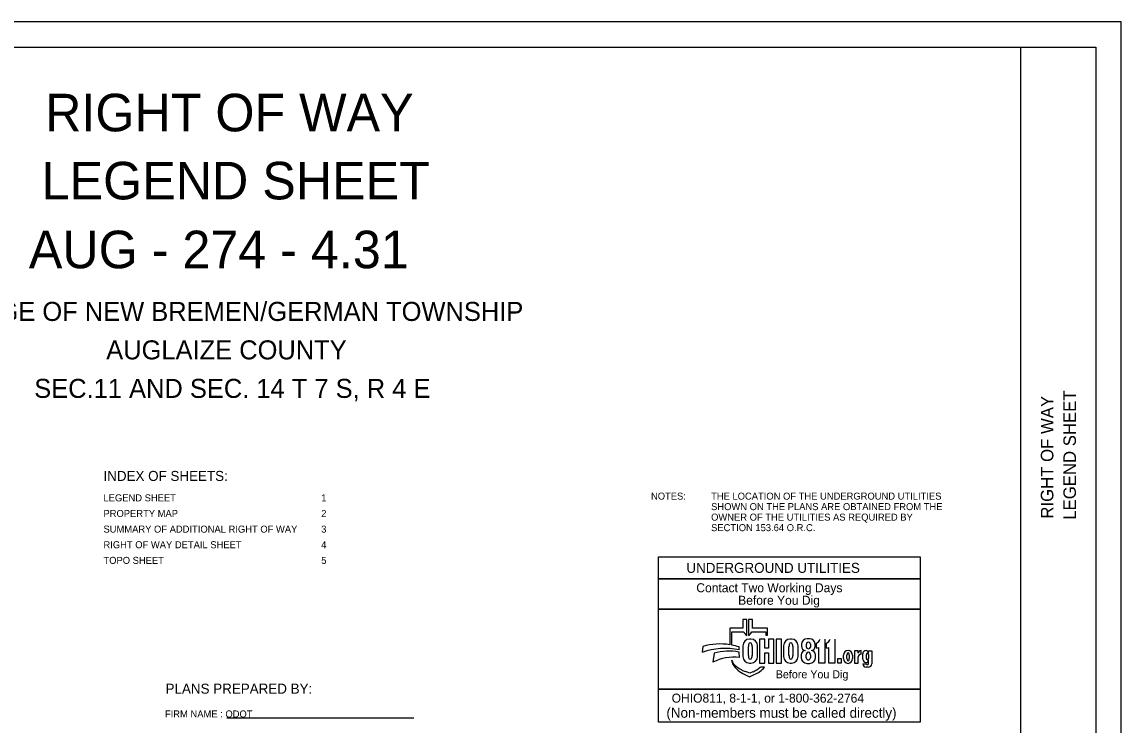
# Model space of a CAD drawing. Extents: x -11.1 to 34, y -3.9 to 22.
# Drawn here: x 12.07 to 34, y 7.96 to 22 of the extents above; entities that cross this region are included whole.
import ezdxf

# ---------------------------------------------------------------- set-up
doc = ezdxf.new("R2010")
doc.units = 0
for name, color, linetype in [('SH_Border', 7, 'Continuous'), ('SH_Cut_Line', 7, 'Continuous'), ('SH_Data', 7, 'Continuous'), ('SH_Text', 7, 'Continuous')]:
    doc.layers.add(name, color=color, linetype=linetype)

msp = doc.modelspace()

# ---------------------------------------------------------------- linework, layer by layer
at = {"layer": 'SH_Border'}
msp.add_line((32, 0.5), (32, 21.5), dxfattribs=at)
msp.add_lwpolyline([(1.5, 21.5), (33.5, 21.5), (33.5, 0.5), (1.5, 0.5)], close=True, dxfattribs=at)
at = {"layer": 'SH_Cut_Line'}
msp.add_lwpolyline([(0, 0), (34, 0), (34, 22), (0, 22)], close=True, dxfattribs=at)
at = {"layer": 'SH_Data'}
for p, q in [((26.455, 9.898), (26.192, 9.898)), ((26.192, 9.898), (26.192, 9.564)), ((26.535, 10.065), (26.455, 10.065)), ((26.455, 10.065), (26.455, 9.898)), ((26.535, 9.748), (26.535, 10.065)), ((26.647, 10.065), (26.566, 10.065)), ((26.566, 10.065), (26.566, 9.748)), ((26.647, 9.898), (26.647, 10.065)), ((26.944, 9.898), (26.647, 9.898)), ((26.944, 9.758), (26.944, 9.898)), ((26.23, 9.557), (26.23, 9.821)), ((26.23, 9.821), (26.471, 9.821)), ((26.612, 9.677), (26.587, 9.677)), ((26.631, 9.821), (26.909, 9.821)), ((26.89, 9.675), (26.788, 9.675)), ((26.788, 9.675), (26.788, 9.197)), ((26.909, 9.821), (26.909, 9.758)), ((26.909, 9.758), (26.944, 9.758)), ((27.423, 9.677), (27.398, 9.677)), ((27.784, 9.683), (27.735, 9.683)), ((28.088, 9.675), (28.088, 9.197)), ((28.288, 9.675), (28.288, 9.197)), ((25.657, 9.529), (25.643, 9.413)), ((26.376, 9.462), (26.376, 9.52)), ((26.454, 9.543), (26.454, 9.331)), ((26.563, 9.348), (26.563, 9.531)), ((26.637, 9.531), (26.637, 9.348)), ((26.746, 9.331), (26.746, 9.543)), ((27.264, 9.543), (27.264, 9.331)), ((27.373, 9.348), (27.373, 9.531)), ((27.448, 9.531), (27.448, 9.348)), ((27.556, 9.331), (27.556, 9.543)), ((27.621, 9.569), (27.621, 9.533)), ((27.72, 9.516), (27.72, 9.575)), ((27.801, 9.575), (27.801, 9.516)), ((27.898, 9.533), (27.898, 9.569)), ((27.921, 9.495), (27.921, 9.597)), ((27.969, 9.197), (27.969, 9.509)), ((28.121, 9.495), (28.121, 9.597)), ((28.169, 9.197), (28.169, 9.509)), ((28.756, 9.441), (28.684, 9.441)), ((28.684, 9.441), (28.684, 9.197)), ((28.756, 9.394), (28.756, 9.441)), ((28.817, 9.449), (28.811, 9.449)), ((28.817, 9.374), (28.817, 9.449)), ((28.96, 9.396), (28.96, 9.442)), ((28.96, 9.442), (29.025, 9.442)), ((29.025, 9.442), (29.025, 9.184)), ((25.878, 9.394), (25.856, 9.215)), ((26.229, 9.258), (26.234, 9.231)), ((26.386, 9.311), (26.377, 9.417)), ((26.89, 9.197), (26.89, 9.4)), ((27.616, 9.363), (27.616, 9.312)), ((27.716, 9.303), (27.716, 9.364)), ((27.801, 9.364), (27.801, 9.303)), ((27.904, 9.312), (27.904, 9.363)), ((28.462, 9.288), (28.462, 9.356)), ((28.529, 9.287), (28.529, 9.356)), ((28.577, 9.356), (28.577, 9.287)), ((28.644, 9.356), (28.644, 9.288)), ((28.756, 9.197), (28.756, 9.325)), ((28.806, 9.374), (28.817, 9.374)), ((28.846, 9.276), (28.846, 9.38)), ((28.918, 9.29), (28.918, 9.366)), ((28.96, 9.366), (28.96, 9.29)), ((28.96, 9.184), (28.96, 9.253)), ((26.594, 8.997), (26.505, 9.027)), ((26.587, 9.197), (26.612, 9.197)), ((26.655, 9.023), (26.594, 8.997)), ((26.788, 9.197), (26.89, 9.197)), ((26.888, 9.117), (26.802, 9.117)), ((26.885, 9.115), (26.888, 9.117)), ((27.398, 9.197), (27.423, 9.197)), ((27.736, 9.191), (27.783, 9.191)), ((28.088, 9.197), (27.969, 9.197)), ((28.288, 9.197), (28.169, 9.197)), ((28.684, 9.197), (28.756, 9.197)), ((28.846, 9.184), (28.918, 9.184)), ((28.956, 9.114), (28.915, 9.114)), ((26.529, 8.951), (26.585, 8.926)), ((26.585, 8.926), (26.68, 8.967)), ((29.991, 8.019), (24.766, 8.019))]:
    msp.add_line(p, q, dxfattribs=at)
for points in [[(24.766, 11.319), (29.991, 11.319), (29.991, 10.879), (24.766, 10.879)], [(24.766, 10.879), (29.991, 10.879), (29.991, 10.274), (24.766, 10.274)], [(24.766, 10.274), (29.991, 10.274), (29.991, 8.679), (24.766, 8.679)], [(28.346, 9.287), (28.412, 9.287), (28.412, 9.197), (28.346, 9.197)], [(24.766, 8.679), (29.991, 8.679), (29.991, 8.019), (24.766, 8.019)]]:
    msp.add_lwpolyline(points, close=True, dxfattribs=at)
for points in [[(26.89, 9.4), (26.966, 9.4), (26.966, 9.197), (27.068, 9.197), (27.068, 9.675), (26.966, 9.675), (26.966, 9.495), (26.89, 9.495), (26.89, 9.675)], [(27.118, 9.197), (27.221, 9.197), (27.221, 9.675), (27.118, 9.675), (27.118, 9.197)], [(27.702, 9.45), (27.702, 9.449)], [(27.817, 9.449), (27.817, 9.45)]]:
    msp.add_lwpolyline(points, dxfattribs=at)
for centre, radius, start, end in [((26.587, 9.543), 0.134, 90, 180), ((26.607, 9.876), 0.147, 201.9296, 240.7469), ((26.495, 9.876), 0.147, 299.2531, 338.0704), ((26.612, 9.543), 0.134, 0, 90), ((27.398, 9.543), 0.134, 90, 180), ((27.423, 9.543), 0.134, 0, 90), ((27.735, 9.569), 0.114, 90, 180), ((27.784, 9.569), 0.114, 0, 90), ((27.87, 9.719), 0.132, 292.5572, 340.7355), ((28.07, 9.719), 0.132, 292.5572, 340.7355), ((26.095, 8.159), 1.332, 77.8238, 109.8274), ((26.001, 8.355), 1.224, 81.0007, 106.3144), ((26.177, 8.342), 1.094, 79.44, 105.8467), ((26.001, 8.355), 1.224, 72.1402, 79.2074), ((27.702, 9.363), 0.0865, 90, 180), ((27.705, 9.533), 0.0837, 180, 268.1442), ((27.814, 9.533), 0.0837, 272.2058, 0), ((27.817, 9.363), 0.0865, 0, 90), ((27.909, 9.627), 0.132, 275.1733, 297.0931), ((28.109, 9.627), 0.132, 275.1733, 297.0931), ((28.557, 9.356), 0.0956, 92.5886, 180), ((28.548, 9.356), 0.0956, 0, 87.4114), ((28.811, 9.394), 0.0548, 90, 180), ((28.914, 9.38), 0.0686, 92.6865, 180), ((28.908, 9.396), 0.0524, 0, 86.9262), ((26.284, 8.367), 0.95, 83.8248, 116.8021), ((26.509, 9.365), 0.3, 201.0457, 232.5314), ((26.445, 9.267), 0.214, 189.6817, 216.0884), ((26.587, 9.331), 0.134, 180, 270), ((26.612, 9.331), 0.134, 270, 0), ((27.398, 9.331), 0.134, 180, 270), ((27.423, 9.331), 0.134, 270, 0), ((27.736, 9.312), 0.121, 180, 270), ((27.783, 9.312), 0.121, 270, 0), ((28.557, 9.288), 0.0956, 180, 267.4114), ((28.548, 9.288), 0.0956, 272.5886, 0), ((28.806, 9.325), 0.0493, 90, 180), ((28.915, 9.276), 0.0692, 180, 265.7132), ((28.914, 9.253), 0.0467, 264.7825, 0), ((26.644, 9.412), 0.461, 216.0884, 235.7167), ((26.797, 9.741), 0.773, 232.5314, 241.794), ((26.893, 9.777), 0.903, 235.7167, 246.2325), ((26.669, 9.503), 0.504, 241.794, 250.9821), ((26.441, 9.517), 0.538, 293.4582, 312.0712), ((26.441, 9.517), 0.599, 293.4582, 317.8286), ((28.915, 9.184), 0.0699, 180, 270), ((28.956, 9.184), 0.0699, 270, 0)]:
    msp.add_arc(centre, radius, start, end, dxfattribs=at)
for centre, major_axis, ratio, start_param, end_param in [((26.6, 9.531), (0, 0.0723), 0.514403, 4.712389, 7.853982), ((27.411, 9.531), (0, 0.0723), 0.514403, 4.712389, 7.853982), ((27.76, 9.575), (0.0404, 0), 0.969373, 0, 3.141593), ((27.76, 9.516), (0.0404, 0), 0.818453, 3.141593, 6.283185), ((26.6, 9.348), (0, 0.0723), 0.514403, 1.570796, 4.712389), ((27.411, 9.348), (0, 0.0723), 0.514403, 1.570796, 4.712389), ((27.759, 9.364), (0, 0.0535), 0.794529, 4.712389, 7.853982), ((27.759, 9.303), (0.0425, 0), 0.959837, 3.141593, 6.283185), ((28.553, 9.356), (0, 0.0434), 0.553236, 4.712389, 7.853982), ((28.553, 9.287), (0, 0.046), 0.522014, 1.570796, 4.712389), ((28.939, 9.366), (0, 0.0275), 0.777179, 4.712389, 7.853982), ((28.939, 9.29), (0, 0.0275), 0.777179, 1.570796, 4.712389), ((28.939, 9.184), (0.0214, 0), 0.959012, 3.141593, 6.283185)]:
    msp.add_ellipse(centre, major_axis=major_axis, ratio=ratio, start_param=start_param, end_param=end_param, dxfattribs=at)
at = {"layer": 'SH_Text'}
msp.add_line((16.151, 8.102), (19.888, 8.102), dxfattribs=at)

# ---------------------------------------------------------------- texts
at = {"layer": 'SH_Data'}
for s, height, p in [('RIGHT OF WAY', 0.75, (12.527, 19.816)), ('LEGEND SHEET', 0.75, (12.458, 18.457)), ('AUG - 274 - 4.31', 0.75, (12.203, 17.082)), ('VILLAGE OF NEW BREMEN/GERMAN TOWNSHIP', 0.38, (10.213, 16.03)), ('AUGLAIZE COUNTY', 0.38, (13.747, 15.262)), ('SEC.11 AND SEC. 14 T 7 S, R 4 E', 0.38, (12.31, 14.493)), ('INDEX OF SHEETS:', 0.2, (13.692, 12.835)), ('LEGEND SHEET', 0.14, (13.692, 12.427)), ('1', 0.14, (18.038, 12.427)), ('PROPERTY MAP', 0.14, (13.692, 12.115)), ('2', 0.14, (18.038, 12.115)), ('SUMMARY OF ADDITIONAL RIGHT OF WAY', 0.14, (13.692, 11.803)), ('3', 0.14, (18.038, 11.803)), ('RIGHT OF WAY DETAIL SHEET', 0.14, (13.692, 11.491)), ('4', 0.14, (18.038, 11.491)), ('TOPO SHEET', 0.14, (13.692, 11.179)), ('5', 0.14, (18.038, 11.179)), ('UNDERGROUND UTILITIES', 0.2, (25.326, 10.999)), ('Contact Two Working Days', 0.18, (25.524, 10.612)), ('Before You Dig', 0.18, (26.359, 10.362)), ('Before You Dig', 0.15972, (27.11, 8.894)), ('OHIO811, 8-1-1, or 1-800-362-2764', 0.18, (25.032, 8.408)), ('(Non-members must be called directly)', 0.2, (24.927, 8.106))]:
    msp.add_text(s, height=height, dxfattribs=at).set_placement(p)
for s, p in [('RIGHT OF WAY', (32.65, 12.082)), ('LEGEND SHEET', (33.1, 12.06))]:
    msp.add_text(s, height=0.25, rotation=90, dxfattribs=at).set_placement(p)
at = {"layer": 'SH_Text'}
for s, height, p in [('NOTES:', 0.14, (24.619, 12.462)), ('THE LOCATION OF THE UNDERGROUND UTILITIES', 0.14, (25.819, 12.462)), ('SHOWN ON THE PLANS ARE OBTAINED FROM THE', 0.14, (25.819, 12.252)), ('OWNER OF THE UTILITIES AS REQUIRED BY', 0.14, (25.819, 12.042)), ('SECTION 153.64 O.R.C.', 0.14, (25.819, 11.832)), ('PLANS PREPARED BY:', 0.2, (14.931, 8.587)), ('FIRM NAME : ODOT', 0.14, (14.919, 8.112))]:
    msp.add_text(s, height=height, dxfattribs=at).set_placement(p)

doc.saveas('drawing.dxf')
